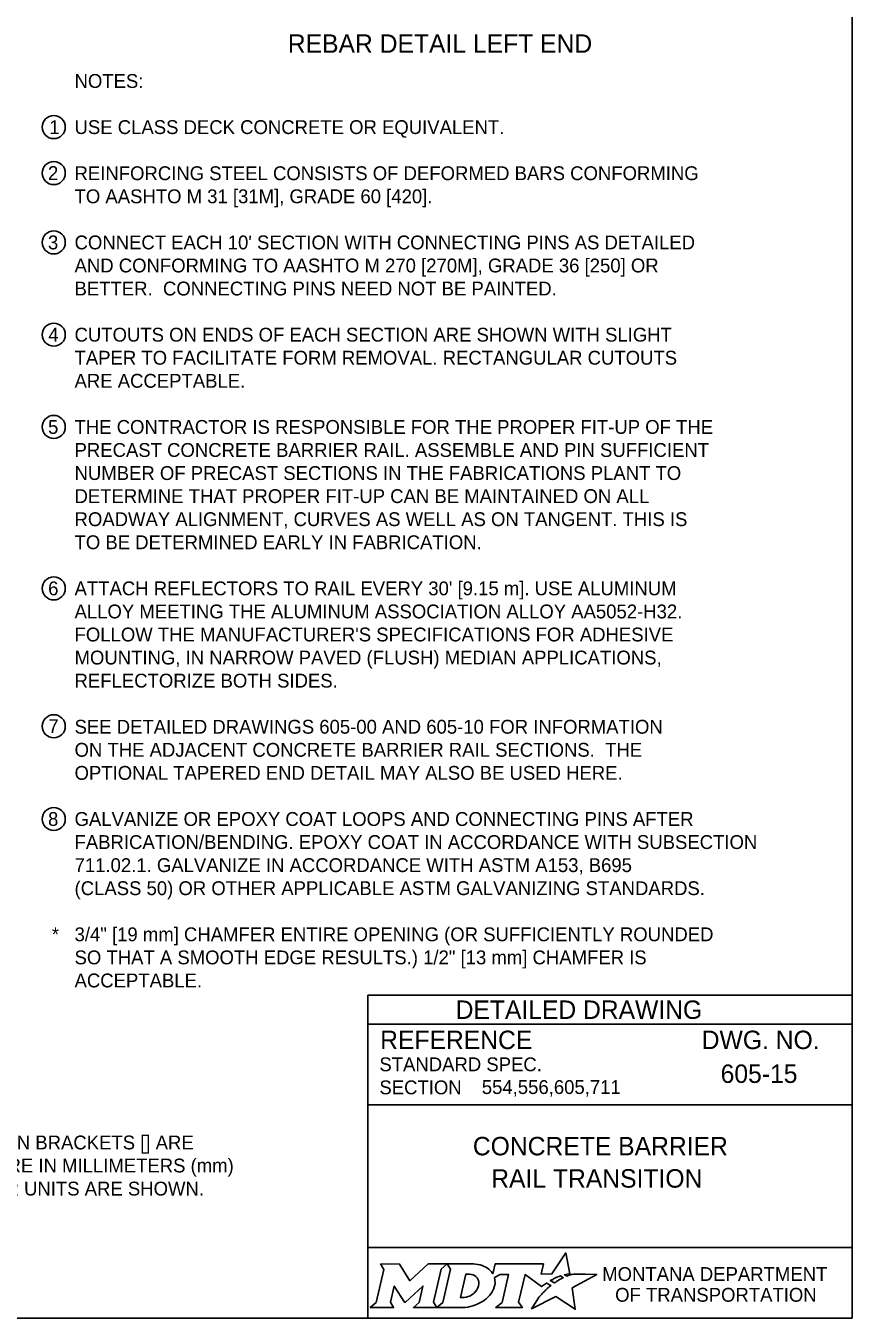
# Model space of a CAD drawing. Extents: x 49991.4 to 50021, y 49987.6 to 50011.4.
# Drawn here: x 50013.17 to 50016.75, y 49987.8 to 49993.4 of the extents above; entities that cross this region are included whole.
import ezdxf

# ---------------------------------------------------------------- set-up
doc = ezdxf.new("R2010")
doc.units = 0
for name, color, linetype in [('Default', 7, 'Continuous'), ('Level 1', 7, 'Continuous'), ('Level 2', 7, 'Continuous'), ('Level 5', 7, 'Continuous')]:
    doc.layers.add(name, color=color, linetype=linetype)

msp = doc.modelspace()

# ---------------------------------------------------------------- linework, layer by layer
at = {"layer": 'Default'}
for points in [[(50015.5126, 49987.9811), (50015.5023, 49987.9867), (50015.5139, 49987.9895), (50015.5255, 49987.9915), (50015.5081, 49988.0816), (50015.4486, 49987.9903), (50015.4013, 49987.9896), (50015.4116, 49988.0337), (50015.2024, 49988.0338), (50015.1923, 49987.9913), (50015.1865, 49987.9996)], [(50014.7056, 49988.0338), (50014.7197, 49988.0104), (50014.6862, 49987.8671), (50014.6605, 49987.8446), (50014.7621, 49987.8446), (50014.7486, 49987.8674), (50014.7648, 49987.9375), (50014.8085, 49987.8685), (50014.8138, 49987.8685), (50014.8889, 49987.938), (50014.8725, 49987.8669), (50014.8478, 49987.8449), (50014.9494, 49987.8449), (50014.9356, 49987.8682), (50014.9688, 49988.0106)], [(50014.9688, 49988.0106), (50014.9941, 49988.0338), (50014.9117, 49988.0338), (50014.8321, 49987.9608), (50014.7876, 49988.0335), (50014.7056, 49988.0338)], [(50015.1077, 49988.0338), (50014.9941, 49988.0338), (50015.0088, 49988.0109), (50014.9749, 49987.8671), (50014.9494, 49987.8449), (50015.06, 49987.8449)], [(50015.1317, 49987.9471), (50015.1305, 49987.939), (50015.1273, 49987.9297), (50015.1231, 49987.9215), (50015.1175, 49987.914), (50015.111, 49987.9071), (50015.1031, 49987.9008), (50015.0948, 49987.8961), (50015.0857, 49987.8922), (50015.0766, 49987.8899), (50015.0674, 49987.889), (50015.0515, 49987.889), (50015.0751, 49987.989), (50015.0911, 49987.989), (50015.0987, 49987.9884), (50015.1063, 49987.9865), (50015.1129, 49987.9835), (50015.119, 49987.9793), (50015.1238, 49987.9743), (50015.1275, 49987.9683), (50015.1302, 49987.9621), (50015.1318, 49987.9547), (50015.1318, 49987.9517), (50015.1317, 49987.9471)], [(50015.1991, 49987.9747), (50015.2237, 49987.9878), (50015.2606, 49987.9878), (50015.232, 49987.8673), (50015.2045, 49987.8446), (50015.3207, 49987.8446), (50015.3037, 49987.8675), (50015.3319, 49987.9877), (50015.4032, 49987.936), (50015.4243, 49987.9511), (50015.444, 49987.9402)], [(50015.3882, 49987.8843), (50015.3729, 49987.8599), (50015.3682, 49987.8524), (50015.3624, 49987.8438), (50015.3601, 49987.8395), (50015.4654, 49987.8926), (50015.5493, 49987.8375), (50015.5362, 49987.9302), (50015.6431, 49987.9886), (50015.5938, 49987.9894), (50015.5637, 49987.9898), (50015.5429, 49987.9901), (50015.5361, 49987.9886), (50015.5312, 49987.9874), (50015.5228, 49987.9851), (50015.5126, 49987.9811)], [(50015.4622, 49987.9535), (50015.4598, 49987.9518), (50015.4415, 49987.9614), (50015.4518, 49987.9671), (50015.4559, 49987.9693), (50015.4645, 49987.9733), (50015.4702, 49987.9759), (50015.4781, 49987.9789), (50015.4854, 49987.9816), (50015.4972, 49987.9742), (50015.4932, 49987.9721), (50015.4886, 49987.9696), (50015.4844, 49987.9674), (50015.4794, 49987.9645), (50015.4775, 49987.9634), (50015.4748, 49987.9618), (50015.4723, 49987.9604), (50015.47, 49987.9588), (50015.4674, 49987.957), (50015.4647, 49987.9552), (50015.4622, 49987.9535)], [(50015.1057, 49987.8522), (50015.1141, 49987.8548), (50015.1271, 49987.8602), (50015.1475, 49987.8712)], [(50015.4021, 49987.9004), (50015.4021, 49987.9004)]]:
    msp.add_lwpolyline(points, dxfattribs=at)
for centre, radius, start, end in [((50015.1308, 49987.9554), 0.0709, 339.5329, 15.8582), ((50015.0868, 49987.9727), 0.1183, 300.9103, 339.1383)]:
    msp.add_arc(centre, radius, start, end, dxfattribs=at)
for centre, major_axis, ratio, start_param, end_param in [((50015.1056, 49987.9864), (0.0834, -0.0037), 0.568097, 0.61298, 1.570796), ((50015.1612, 49987.9937), (0.0361, -0.0295), 0.469099, 1.225588, 1.570796), ((50015.4119, 49987.9106), (-0.0098, -0.0102), 0.016458, 3.141593, 6.279097), ((50015.4329, 49987.9305), (-0.0112, -0.0097), 0.021651, 3.157348, 6.283185), ((50015.3952, 49987.8923), (-0.00694, -0.00806), 0.008222, 0, 3.137361), ((50015.0603, 49987.9932), (0, 0.1484), 0.987302, 3.139398, 3.456847)]:
    msp.add_ellipse(centre, major_axis=major_axis, ratio=ratio, start_param=start_param, end_param=end_param, dxfattribs=at)
at = {"layer": 'Level 1'}
msp.add_lwpolyline([(49999.3835, 49998.9992), (50016.7501, 49998.9992), (50016.7501, 49987.7988), (49999.3835, 49987.7988)], close=True, dxfattribs=at)
at = {"layer": 'Level 2'}
for centre in [(50013.2887, 49992.963), (50013.2887, 49992.7636), (50013.2887, 49992.463), (50013.2887, 49992.063), (50013.2887, 49991.663), (50013.2887, 49990.963), (50013.2887, 49990.3653), (50013.2887, 49989.963)]:
    msp.add_circle(centre, 0.05, dxfattribs=at)
at = {"layer": 'Level 5'}
for p, q in [((50016.7501, 49989.1988), (50014.6501, 49989.1988)), ((50014.6501, 49989.1988), (50014.6501, 49987.7988)), ((50016.7501, 49989.0738), (50014.6501, 49989.0738)), ((50016.3862, 49988.8587), (50016.3862, 49988.8587)), ((50015.1444, 49988.7993), (50015.1444, 49988.7993)), ((50016.7501, 49988.7238), (50014.6501, 49988.7238)), ((50015.7001, 49988.4747), (50015.7001, 49988.4747)), ((50016.7501, 49988.1057), (50014.6501, 49988.1057))]:
    msp.add_line(p, q, dxfattribs=at)

# ---------------------------------------------------------------- texts
at = {"layer": 'Default'}
for s, p in [('MONTANA DEPARTMENT', (50015.6663, 49987.96)), ('OF TRANSPORTATION', (50015.7225, 49987.87))]:
    msp.add_text(s, height=0.06, dxfattribs=at).set_placement(p)
at = {"layer": 'Level 2'}
for s, height, p in [('REBAR DETAIL LEFT END', 0.08, (50014.3033, 49993.2851)), ('NOTES:', 0.06, (50013.3787, 49993.133)), ('1', 0.06, (50013.269, 49992.933)), ('USE CLASS DECK CONCRETE OR EQUIVALENT.', 0.06, (50013.3787, 49992.933)), ('2', 0.06, (50013.2636, 49992.7336)), ('REINFORCING STEEL CONSISTS OF DEFORMED BARS CONFORMING ', 0.06, (50013.3787, 49992.733)), ('TO AASHTO M 31 [31M], GRADE 60 [420].', 0.06, (50013.3787, 49992.633)), ('3', 0.06, (50013.2635, 49992.433)), ("CONNECT EACH 10' SECTION WITH CONNECTING PINS AS DETAILED", 0.06, (50013.3787, 49992.433)), ('AND CONFORMING TO AASHTO M 270 [270M], GRADE 36 [250] OR ', 0.06, (50013.3787, 49992.333)), ('BETTER.  CONNECTING PINS NEED NOT BE PAINTED.', 0.06, (50013.3787, 49992.233)), ('4', 0.06, (50013.2648, 49992.033)), ('CUTOUTS ON ENDS OF EACH SECTION ARE SHOWN WITH SLIGHT', 0.06, (50013.3787, 49992.033)), ('TAPER TO FACILITATE FORM REMOVAL. RECTANGULAR CUTOUTS', 0.06, (50013.3787, 49991.933)), ('ARE ACCEPTABLE.', 0.06, (50013.3787, 49991.833)), ('5', 0.06, (50013.2638, 49991.633)), ('THE CONTRACTOR IS RESPONSIBLE FOR THE PROPER FIT-UP OF THE', 0.06, (50013.3787, 49991.633)), ('PRECAST CONCRETE BARRIER RAIL. ASSEMBLE AND PIN SUFFICIENT', 0.06, (50013.3787, 49991.533)), ('NUMBER OF PRECAST SECTIONS IN THE FABRICATIONS PLANT TO', 0.06, (50013.3787, 49991.433)), ('DETERMINE THAT PROPER FIT-UP CAN BE MAINTAINED ON ALL', 0.06, (50013.3787, 49991.333)), ('ROADWAY ALIGNMENT, CURVES AS WELL AS ON TANGENT. THIS IS', 0.06, (50013.3787, 49991.233)), ('TO BE DETERMINED EARLY IN FABRICATION.', 0.06, (50013.3787, 49991.133)), ("ATTACH REFLECTORS TO RAIL EVERY 30' [9.15 m]. USE ALUMINUM", 0.06, (50013.3787, 49990.933)), ('6', 0.06, (50013.2642, 49990.933)), ('ALLOY MEETING THE ALUMINUM ASSOCIATION ALLOY AA5052-H32. ', 0.06, (50013.3787, 49990.833)), ("FOLLOW THE MANUFACTURER'S SPECIFICATIONS FOR ADHESIVE ", 0.06, (50013.3787, 49990.733)), ('MOUNTING, IN NARROW PAVED (FLUSH) MEDIAN APPLICATIONS, ', 0.06, (50013.3787, 49990.633)), ('REFLECTORIZE BOTH SIDES.', 0.06, (50013.3787, 49990.533)), ('7', 0.06, (50013.2649, 49990.3353)), ('SEE DETAILED DRAWINGS 605-00 AND 605-10 FOR INFORMATION', 0.06, (50013.3787, 49990.333)), ('ON THE ADJACENT CONCRETE BARRIER RAIL SECTIONS.  THE', 0.06, (50013.3787, 49990.233)), ('OPTIONAL TAPERED END DETAIL MAY ALSO BE USED HERE.', 0.06, (50013.3787, 49990.133)), ('8', 0.06, (50013.2637, 49989.933)), ('GALVANIZE OR EPOXY COAT LOOPS AND CONNECTING PINS AFTER', 0.06, (50013.3787, 49989.933)), ('FABRICATION/BENDING. EPOXY COAT IN ACCORDANCE WITH SUBSECTION', 0.06, (50013.3787, 49989.833)), ('711.02.1. GALVANIZE IN ACCORDANCE WITH ASTM A153, B695 ', 0.06, (50013.3787, 49989.733)), ('(CLASS 50) OR OTHER APPLICABLE ASTM GALVANIZING STANDARDS. ', 0.06, (50013.3787, 49989.633)), ('*', 0.06, (50013.2802, 49989.433)), ('3/4" [19 mm] CHAMFER ENTIRE OPENING (OR SUFFICIENTLY ROUNDED', 0.06, (50013.3787, 49989.433)), ('SO THAT A SMOOTH EDGE RESULTS.) 1/2" [13 mm] CHAMFER IS', 0.06, (50013.3787, 49989.333)), ('ACCEPTABLE.', 0.06, (50013.3787, 49989.233)), ('605-15', 0.08, (50016.1799, 49988.8187)), ('554,556,605,711', 0.06, (50015.1444, 49988.7707)), ('UNITS SHOWN IN BRACKETS [] ARE ', 0.06, (50012.5132, 49988.5305)), ('CONCRETE BARRIER', 0.08, (50015.1056, 49988.5047)), ('METRIC AND ARE IN MILLIMETERS (mm) ', 0.06, (50012.5132, 49988.4305)), ('RAIL TRANSITION', 0.08, (50015.1853, 49988.3647)), ('UNLESS OTHER UNITS ARE SHOWN.', 0.06, (50012.5132, 49988.3305))]:
    msp.add_text(s, height=height, dxfattribs=at).set_placement(p)
at = {"layer": 'Level 5'}
for s, height, p in [('DETAILED DRAWING', 0.0799, (50015.0311, 49989.0963)), ('REFERENCE', 0.08, (50014.7037, 49988.9654)), ('DWG. NO.', 0.08, (50016.0979, 49988.9654)), ('STANDARD SPEC.', 0.06, (50014.7004, 49988.8694)), ('SECTION', 0.06, (50014.7004, 49988.7694))]:
    msp.add_text(s, height=height, dxfattribs=at).set_placement(p)

doc.saveas('drawing.dxf')
